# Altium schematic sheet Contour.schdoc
size 343 x 127 mm; Symbol: Drawing-Symbol_A4; @Project Name: Assisant vocal; @Page Count: 1; @Update Date: 2026-03-31; @Create Date: 2026-03-26; @Schematic Name: Contour; @Page No: 1; @Page Name: Contour; Company: EasyEDA.com; Version: V1.0; Page Size: A4; @Create Time: 16:17:31; @Update Time: 16:29:56; Border: 1; Width: 1350; Height: 500; Region Start: 1; X Region Count: 6; Y Region Count: 4; Blade Width: 10; Title Block Position: 3; @Board Name: Contour; Device: Drawing-Symbol_A4
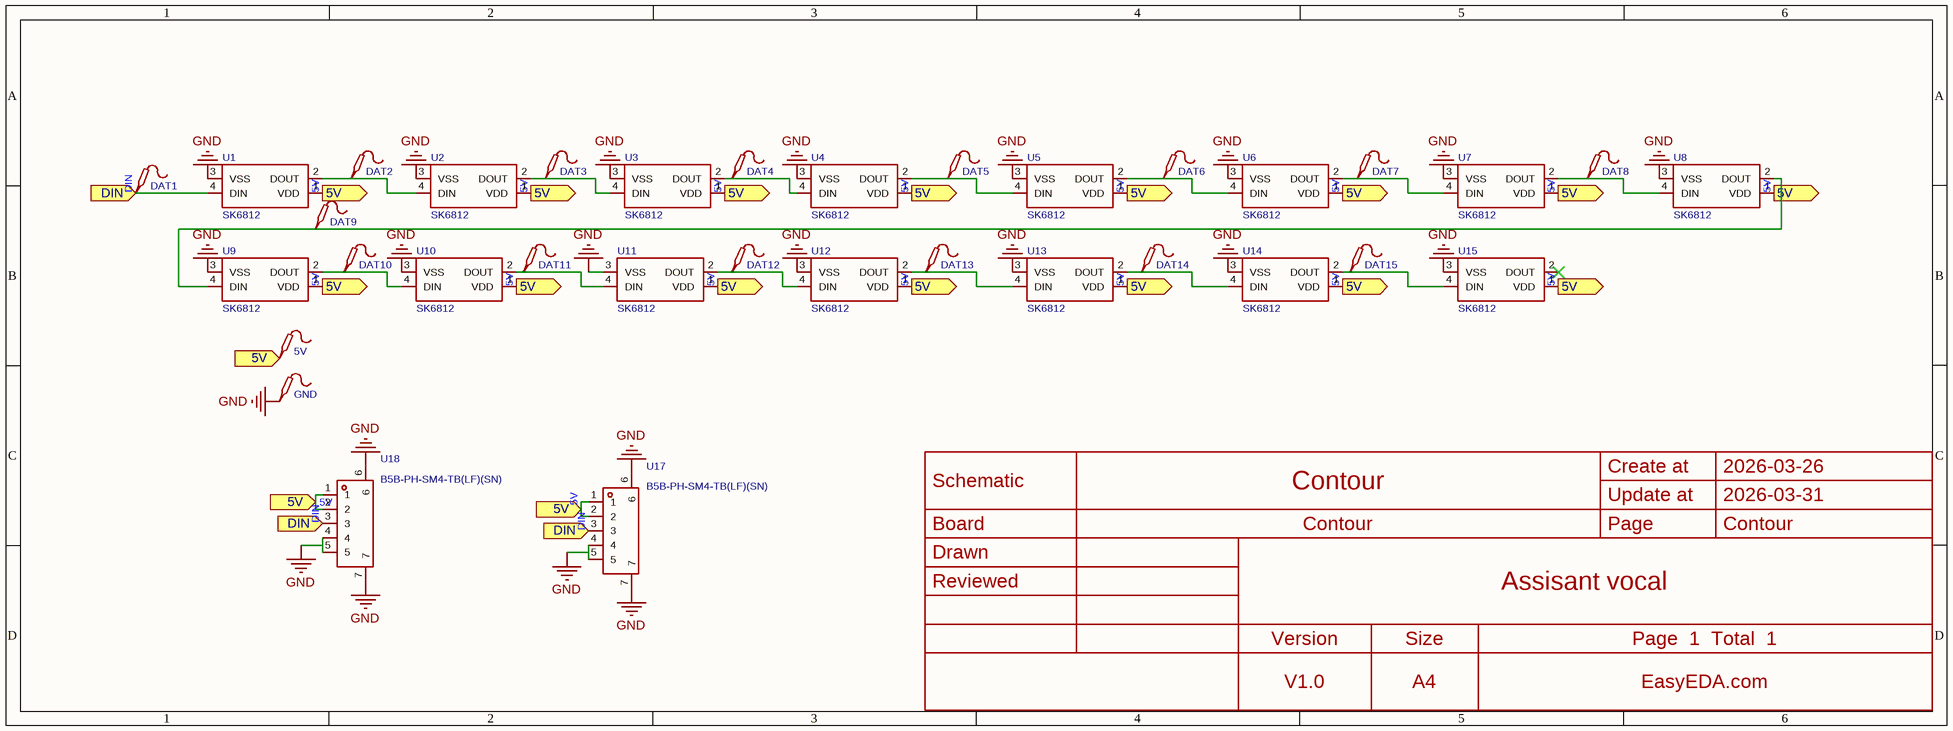
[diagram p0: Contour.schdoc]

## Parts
5V  (no value)  [Test-Point-0.5mm]
DAT1  (no value)  [Test-Point-0.5mm]
DAT2  (no value)  [Test-Point-0.5mm]
DAT3  (no value)  [Test-Point-0.5mm]
DAT4  (no value)  [Test-Point-0.5mm]
DAT5  (no value)  [Test-Point-0.5mm]
DAT6  (no value)  [Test-Point-0.5mm]
DAT7  (no value)  [Test-Point-0.5mm]
DAT8  (no value)  [Test-Point-0.5mm]
DAT9  (no value)  [Test-Point-0.5mm]
DAT10  (no value)  [Test-Point-0.5mm]
DAT11  (no value)  [Test-Point-0.5mm]
DAT12  (no value)  [Test-Point-0.5mm]
DAT13  (no value)  [Test-Point-0.5mm]
DAT14  (no value)  [Test-Point-0.5mm]
DAT15  (no value)  [Test-Point-0.5mm]
GND  (no value)  [Test-Point-0.5mm]
U1  SK6812  [LED-SMD_4P-L5.0-W5.0-LS5.4-TL-1]
U2  SK6812  [LED-SMD_4P-L5.0-W5.0-LS5.4-TL-1]
U3  SK6812  [LED-SMD_4P-L5.0-W5.0-LS5.4-TL-1]
U4  SK6812  [LED-SMD_4P-L5.0-W5.0-LS5.4-TL-1]
U5  SK6812  [LED-SMD_4P-L5.0-W5.0-LS5.4-TL-1]
U6  SK6812  [LED-SMD_4P-L5.0-W5.0-LS5.4-TL-1]
U7  SK6812  [LED-SMD_4P-L5.0-W5.0-LS5.4-TL-1]
U8  SK6812  [LED-SMD_4P-L5.0-W5.0-LS5.4-TL-1]
U9  SK6812  [LED-SMD_4P-L5.0-W5.0-LS5.4-TL-1]
U10  SK6812  [LED-SMD_4P-L5.0-W5.0-LS5.4-TL-1]
U11  SK6812  [LED-SMD_4P-L5.0-W5.0-LS5.4-TL-1]
U12  SK6812  [LED-SMD_4P-L5.0-W5.0-LS5.4-TL-1]
U13  SK6812  [LED-SMD_4P-L5.0-W5.0-LS5.4-TL-1]
U14  SK6812  [LED-SMD_4P-L5.0-W5.0-LS5.4-TL-1]
U15  SK6812  [LED-SMD_4P-L5.0-W5.0-LS5.4-TL-1]
U17  B5B-PH-SM4-TB(LF)(SN)  [CONN-SMD_5P-P2.00_B6B-PH-SM4-TB-LF-SN]
U18  B5B-PH-SM4-TB(LF)(SN)  [CONN-SMD_5P-P2.00_B6B-PH-SM4-TB-LF-SN]

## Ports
5V (in), 5V (out), DIN (in)

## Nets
GND: GND.1 U1.3(VSS) U2.3(VSS) U3.3(VSS) U4.3(VSS) U5.3(VSS) U6.3(VSS) U7.3(VSS) U8.3(VSS) U9.3(VSS) U10.3(VSS) U11.3(VSS) U12.3(VSS) U13.3(VSS) U14.3(VSS) U15.3(VSS) U17.4 U17.5 U17.6 U17.7 U18.4 U18.5 U18.6 U18.7
5V: 5V.1 U1.1(VDD) U2.1(VDD) U3.1(VDD) U4.1(VDD) U5.1(VDD) U6.1(VDD) U7.1(VDD) U8.1(VDD) U9.1(VDD) U10.1(VDD) U11.1(VDD) U12.1(VDD) U13.1(VDD) U14.1(VDD) U15.1(VDD) U17.1 U17.2 U18.1 U18.2 ; port 5V
DIN: DAT1.1 U1.4(DIN) U17.3 U18.3 ; port DIN
NetDAT2_1: DAT2.1 U1.2(DOUT) U2.4(DIN)
NetDAT3_1: DAT3.1 U2.2(DOUT) U3.4(DIN)
NetDAT4_1: DAT4.1 U3.2(DOUT) U4.4(DIN)
NetDAT5_1: DAT5.1 U4.2(DOUT) U5.4(DIN)
NetDAT6_1: DAT6.1 U5.2(DOUT) U6.4(DIN)
NetDAT7_1: DAT7.1 U6.2(DOUT) U7.4(DIN)
NetDAT8_1: DAT8.1 U7.2(DOUT) U8.4(DIN)
NetDAT9_1: DAT9.1 U8.2(DOUT) U9.4(DIN)
NetDAT10_1: DAT10.1 U9.2(DOUT) U10.4(DIN)
NetDAT11_1: DAT11.1 U10.2(DOUT) U11.4(DIN)
NetDAT12_1: DAT12.1 U11.2(DOUT) U12.4(DIN)
NetDAT13_1: DAT13.1 U12.2(DOUT) U13.4(DIN)
NetDAT14_1: DAT14.1 U13.2(DOUT) U14.4(DIN)
NetDAT15_1: DAT15.1 U14.2(DOUT) U15.4(DIN)

Not connected (* = marked no-connect by the designer): U15 2(DOUT)*

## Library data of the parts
5V DAT1-DAT15 GND = Test-Point: Test Point 测试点; AddInBom: yes
U1-U15 = SK6812_C5378720: Wavelength:R:620nm~625nm；B:460nm~470nm；G:520nm~530nm Luminous Intensity:B:160mcd~320mcd；R:280mcd~515mcd；G:815mcd~1275mcd Fixed-Frequency Pwm Mode:1kHz Data Transmission Rate:800Kbit/s Voltage - Supply:3.7V~5.5V Voltage - Supply:3.7V~5.5V Quiescent Current; Manufacturer: 欧思科光电; AddInBom: yes; ModelId: f511df006eb14ecdbc9bf2fa9b259b61; ModelTransform: 214.96,196.85,0,0,0,0,0,0,0; Fixed-Frequency Pwm Mode: 1kHz; Quiescent Current: 0.6mA; Lens Color: Semi-transparent lens; ESD Withstand Voltage: 2000V; Viewing Angle: 120°
U17 U18 = B5B-PH-SM4-TB(LF)(SN): Pins Structure:1x5P Pitch:2mm Mounting Type:Surface Mount,Vertical Reference Series:PH Number of Pins:5P Number of Rows:1 Number of PINs Per Row:5 Row Spacing:- Current Rating:2A Contact Material:Copper Alloy Contact Plating:Tin Operating Temperature:-25℃; Manufacturer: JST; AddInBom: yes; ModelId: 42661aa5dd484b92a752559c239d11dd; ModelTransform: 551.18,295.275,0,0,0,0,0,3.425,0; Pins Structure: 1x5P; Pitch: 2mm; Reference Series: PH; Number of PINs Per Row: 5; Current Rating: 2A; Voltage Rating: 100V; Plastic Material: PA; Flame Retardant Rating: UL94V-0; Supplementary Features: Auxiliary Solder Pin; Z-Height of the Board: 6.6mm; X-Length of Bottom Edge on Board (Spacing Line): 13.95mm; Y-Width of Bottom Edge on Board: 7mm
